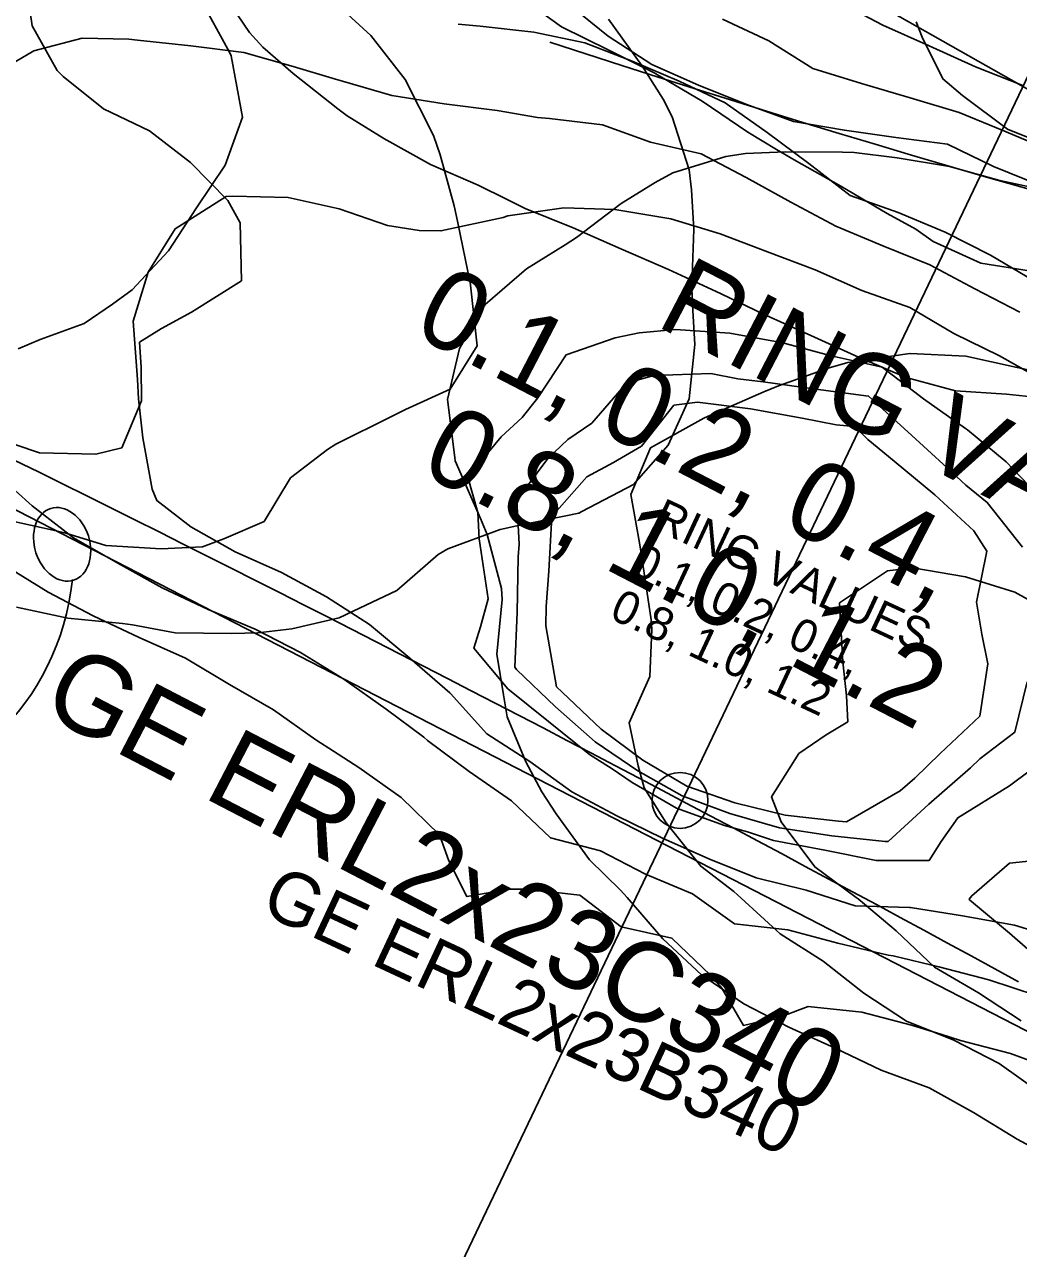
# Model space of a CAD drawing. Extents: x 1638506 to 1658005, y 834807 to 846788.
# Drawn here: x 1640119.8 to 1640269.4, y 842523.2 to 842707.5 of the extents above; entities that cross this region are included whole.
import ezdxf

# ---------------------------------------------------------------- set-up
doc = ezdxf.new("R2010")
doc.units = 0
for name, color, linetype in [('Default', 7, 'Continuous'), ('Old_Level_1', 7, 'Continuous'), ('Old_Level_2', 7, 'Continuous'), ('Scratch_Level_0', 7, 'Continuous')]:
    doc.layers.add(name, color=color, linetype=linetype)

msp = doc.modelspace()

# ---------------------------------------------------------------- linework, layer by layer
at = {"layer": 'Default'}
for p, q in [((1640114.23, 842786.79), (1640314.63, 842672.83)), ((1640060.76, 842664.16), (1640296.3, 842542.72))]:
    msp.add_line(p, q, dxfattribs=at)
msp.add_ellipse((1640125.45, 842629.26), major_axis=(-1.72, 5.4), ratio=0.730797, dxfattribs=at)
msp.add_ellipse((1640097.39, 842627.23), major_axis=(3.78, 34.34), ratio=0.862742, start_param=3.141593, end_param=4.712389, dxfattribs=at)
at = {"layer": 'Old_Level_1'}
for points in [[(1640150.91, 842702.81), (1640150.68, 842703.26), (1640146.14, 842711.64), (1640144.46, 842714.27), (1640140.93, 842718.55), (1640135.28, 842724.54), (1640129.23, 842729.66), (1640128.89, 842729.97), (1640123.18, 842734.8), (1640116.77, 842739.16)], [(1640242.12, 842711.05), (1640248.95, 842707.43), (1640255.95, 842704.3), (1640262.94, 842701.14), (1640270.07, 842698.37)], [(1640201.34, 842710.84), (1640207.64, 842705.78), (1640214.23, 842701.51), (1640221.23, 842698.38), (1640228.34, 842695.55), (1640235.53, 842692.94), (1640243.19, 842691.62), (1640250.92, 842690.5), (1640258.7, 842689.5), (1640265.63, 842686.17), (1640272.72, 842683.27)], [(1640271.78, 842668.87), (1640265.17, 842672.79), (1640258.36, 842676.29), (1640251.3, 842679.25), (1640244.05, 842681.8), (1640237.84, 842686.59), (1640231.58, 842691.26), (1640225.23, 842695.75), (1640218.3, 842698.98), (1640211.27, 842702.01), (1640204.1, 842704.75), (1640196.43, 842706.39), (1640188.39, 842707.26), (1640185.06, 842707.56)], [(1640224.85, 842708.32), (1640231.8, 842705.06), (1640238.43, 842700.9), (1640245.75, 842698.64), (1640253.11, 842696.5), (1640260.45, 842694.3), (1640267.53, 842691.39), (1640274.58, 842688.4)], [(1640269.62, 842664.23), (1640262.82, 842667.75), (1640256.05, 842671.34), (1640248.95, 842674.22), (1640241.88, 842677.16), (1640235.14, 842680.8), (1640228.42, 842684.49), (1640221.65, 842688.07), (1640214.02, 842689.81), (1640206.8, 842692.43), (1640198.79, 842693.36), (1640196.99, 842693.55), (1640190.92, 842694.58), (1640182.94, 842695.57), (1640175.09, 842696.83), (1640167.66, 842699), (1640166.58, 842699.29), (1640160.24, 842701.19), (1640152.79, 842703.31), (1640144.82, 842704.33), (1640136.79, 842705.2), (1640135.49, 842705.35), (1640128.47, 842705.47), (1640121.19, 842703.57), (1640118.36, 842701.89)], [(1640118.85, 842658.68), (1640122.12, 842660.1), (1640128.79, 842662.49), (1640133.02, 842665.4), (1640135.97, 842667.58), (1640141.47, 842673.46), (1640145.67, 842679.94), (1640150.01, 842686.35), (1640152.58, 842693.6), (1640150.91, 842702.81)], [(1640273.23, 842653.88), (1640266.54, 842657.64), (1640259.68, 842661.02), (1640253.05, 842664.91), (1640245.81, 842667.48), (1640238.81, 842670.57), (1640231.63, 842673.28), (1640224.47, 842676.01), (1640217.08, 842678.28), (1640209.25, 842679.58), (1640208.65, 842679.67), (1640200.97, 842679.93), (1640192.55, 842678.74), (1640191.84, 842678.46), (1640182.47, 842676.46), (1640179.17, 842676.54), (1640174.4, 842677.25), (1640167.15, 842679.8), (1640159.49, 842681.47), (1640151.14, 842681.68), (1640150.16, 842681.63), (1640142.46, 842676.77), (1640138.39, 842670.23), (1640136.12, 842662.85), (1640136.78, 842654.1), (1640136.92, 842651.18), (1640137.59, 842645.28), (1640139.02, 842637.58), (1640139.69, 842635.86), (1640144.81, 842631.91), (1640151.48, 842628.11), (1640158.48, 842625), (1640165.23, 842621.38), (1640171.72, 842617.19), (1640177.78, 842612.1), (1640183.8, 842606.9), (1640183.9, 842606.81), (1640189.35, 842600.71), (1640195.86, 842596.57), (1640202.17, 842591.99), (1640208.93, 842588.39), (1640215.79, 842585), (1640222.8, 842581.92), (1640229.9, 842579.06), (1640237.46, 842577.17), (1640244.82, 842574.84), (1640252.99, 842574.59), (1640253.13, 842574.57), (1640260.98, 842573.3), (1640268.78, 842571.93), (1640276.16, 842569.65)], [(1640273.22, 842635.75), (1640267.53, 842641.66), (1640261.71, 842646.49), (1640261.44, 842646.7), (1640255.08, 842651.15), (1640248.87, 842655.94), (1640241.21, 842657.62), (1640233.71, 842659.63), (1640233.38, 842659.7), (1640225.93, 842661.06), (1640217.75, 842661.62), (1640212.29, 842661.1), (1640208.71, 842660.33), (1640201.31, 842657.77), (1640197.07, 842651.31), (1640194.7, 842648.38), (1640191.54, 842645.45), (1640186.49, 842639.36), (1640188.01, 842634.04), (1640188.24, 842630.1), (1640189.57, 842621.05), (1640188.43, 842616.83), (1640187.41, 842613.61), (1640192.53, 842607.51), (1640198.67, 842602.6), (1640204.8, 842597.63), (1640208.26, 842595.45), (1640211.26, 842593.39), (1640217.91, 842589.54), (1640225.13, 842586.92), (1640228.63, 842585.95), (1640232.53, 842584.69), (1640240.27, 842583.2), (1640247.99, 842581.65), (1640255.94, 842581.65), (1640257.76, 842584.5), (1640260.26, 842588.08), (1640268.05, 842592.89), (1640271.21, 842595.25)], [(1640269.98, 842628.81), (1640264.7, 842635.58), (1640261.45, 842638.17), (1640258.68, 842640.78), (1640252.76, 842646.18), (1640246.84, 842651.58), (1640238.89, 842652.65), (1640230.95, 842653.71), (1640227.17, 842654.16), (1640223.1, 842654.98), (1640214.52, 842654.68), (1640210.37, 842653.55), (1640205.18, 842647.53), (1640201.58, 842645.03), (1640198.55, 842642.18), (1640193.91, 842635.9), (1640194.24, 842629.29), (1640194.11, 842627.37), (1640193.94, 842619), (1640193.57, 842610.74), (1640193.86, 842610.39), (1640199.69, 842604.79), (1640205.68, 842599.52), (1640212.1, 842595.18), (1640218.78, 842591.41), (1640225.96, 842588.72), (1640233.41, 842586.59), (1640241.29, 842585.39), (1640249.33, 842584.52), (1640249.79, 842584.52), (1640255.88, 842590.12), (1640262.18, 842595.63), (1640263.57, 842596.96), (1640268.84, 842600.96), (1640270.68, 842608.54)], [(1640264.79, 842611.29), (1640263.89, 842615.74), (1640263.06, 842620.54), (1640264.63, 842628.25), (1640262.69, 842631.27), (1640256.79, 842636.73), (1640250.7, 842641.77), (1640246.7, 842645.05), (1640244.71, 842647.02), (1640241.93, 842647.27), (1640236.84, 842648.24), (1640229.06, 842649.66), (1640221.09, 842650.67), (1640217.52, 842650.21), (1640212.63, 842644.05), (1640208.42, 842641.6), (1640204.44, 842639.43), (1640199.17, 842633.45), (1640198.71, 842625.22), (1640198.31, 842619.91), (1640198.25, 842617), (1640199.87, 842607.8), (1640200.72, 842606.98), (1640206.56, 842601.42), (1640212.84, 842596.78), (1640219.45, 842592.85), (1640226.71, 842590.32), (1640234.3, 842588.49), (1640242.32, 842587.58), (1640243.49, 842587.46), (1640251.57, 842592.13), (1640253.77, 842594.05), (1640257.58, 842597.77), (1640263.59, 842603.41), (1640264.79, 842611.29)], [(1640118.37, 842637.36), (1640120.95, 842635.04), (1640127.16, 842630.25), (1640133.82, 842626.44), (1640140.52, 842622.7), (1640147.45, 842619.46), (1640154.51, 842616.5), (1640161.31, 842612.98), (1640167.87, 842608.95), (1640174.21, 842604.44), (1640179.91, 842600.23), (1640180.45, 842599.71), (1640186.73, 842595.08), (1640193.09, 842590.62), (1640198.93, 842585.05), (1640206.46, 842583.09), (1640213.27, 842579.6), (1640220.33, 842576.63), (1640226.67, 842572.12), (1640234.69, 842571.22), (1640242.19, 842569.21), (1640249.78, 842567.38), (1640250.52, 842567.3), (1640257.41, 842565.64), (1640264.94, 842563.69), (1640272.24, 842561.26)], [(1640116.79, 842626.12), (1640123.33, 842622.05), (1640130.13, 842618.51), (1640137.04, 842615.24), (1640144.04, 842612.14), (1640150.62, 842608.15), (1640157.27, 842604.32), (1640163.61, 842599.82), (1640166.28, 842598.14), (1640170.11, 842595.65), (1640176.46, 842591.16), (1640182.27, 842585.52), (1640183.63, 842581.61), (1640186.38, 842576.22), (1640192.78, 842577.34), (1640195.33, 842577.32), (1640203.36, 842576.44), (1640209.58, 842571.68), (1640217.22, 842569.97), (1640223.06, 842564.39), (1640224.72, 842562.45), (1640227.98, 842556.83), (1640233.86, 842558.19), (1640237.74, 842559.66), (1640245.79, 842558.83), (1640253.31, 842556.85), (1640257.68, 842555.52), (1640260.68, 842554.56), (1640268.21, 842552.59), (1640275.41, 842549.95)]]:
    msp.add_lwpolyline(points, dxfattribs=at)
msp.add_circle((1640218.45, 842590.7), 4.21, dxfattribs=at)
at = {"layer": 'Old_Level_2'}
msp.add_line((1640319.78, 842802.51), (1640164.82, 842477.58), dxfattribs=at)
for centre, radius, start, end in [((1640787.74, 844492.39), 1882, 251.76578, 273.94492), ((1638364.53, 839083.08), 3967.5, 61.30704, 65.05582)]:
    msp.add_arc(centre, radius, start, end, dxfattribs=at)
at = {"layer": 'Scratch_Level_0'}
for points in [[(1640186.93, 842668.27), (1640186.91, 842668.37), (1640184.98, 842677.91), (1640184.46, 842680.23), (1640182.35, 842687.89), (1640181.33, 842690.81), (1640177.08, 842699.23), (1640177.06, 842699.26), (1640171.92, 842705.88), (1640166.08, 842711.23), (1640160.28, 842716.6), (1640160.26, 842716.62), (1640154.71, 842722.53), (1640149.4, 842728.92), (1640145.99, 842732.64), (1640143.88, 842734.89), (1640138.25, 842740.64), (1640132.68, 842746.51), (1640129.19, 842749.98), (1640127.18, 842752.52), (1640121.22, 842757.64), (1640114.3, 842760.92)], [(1640152.23, 842677.67), (1640150.4, 842681.05), (1640144.75, 842686.76), (1640138.59, 842691.5), (1640131.7, 842694.83), (1640125.6, 842699.69), (1640124.7, 842700.6), (1640120.95, 842707.33), (1640120.34, 842711.48), (1640120.44, 842720.05), (1640120.21, 842722.51), (1640119, 842729.42)], [(1640148.97, 842713.26), (1640153.64, 842706.31), (1640155.68, 842704.12), (1640160.21, 842700.17), (1640166.95, 842694.85), (1640168.35, 842693.79), (1640173.86, 842690.37), (1640180.88, 842686.45), (1640188.06, 842683.35), (1640192.41, 842681.2), (1640195.16, 842679.82), (1640202.39, 842676.94), (1640209.56, 842673.78), (1640216.73, 842670.63), (1640223.87, 842667.32), (1640224.62, 842666.98), (1640231, 842663.94), (1640238.16, 842660.72), (1640245.31, 842657.45), (1640252.49, 842654.38), (1640259.9, 842652.39), (1640267.6, 842651.88), (1640275.23, 842651.06)], [(1640193.83, 842712.12), (1640200.62, 842707.19), (1640207.71, 842703.67), (1640214.78, 842700.14), (1640214.81, 842700.13), (1640221.78, 842695.99), (1640228.66, 842691.33), (1640232.97, 842688.71), (1640235.62, 842687.14), (1640242.63, 842683.18), (1640249.62, 842679.1), (1640253.94, 842676.74), (1640256.57, 842674.86), (1640263.73, 842671.6), (1640271.28, 842670.38)], [(1640220.69, 842659.36), (1640220.27, 842666.19), (1640220.22, 842668.22), (1640220.54, 842676.67), (1640220.19, 842682.64), (1640219.83, 842685.67), (1640217.28, 842693.64), (1640215.93, 842696.31), (1640212.68, 842701.37), (1640207.69, 842708.36)], [(1640254, 842707.92), (1640254.91, 842705.63), (1640257.99, 842699.33), (1640260.96, 842696.84), (1640267.74, 842691.75), (1640274.97, 842688.86)], [(1640271.32, 842683.02), (1640266.58, 842684.06), (1640259.03, 842686.14), (1640251.11, 842687.47), (1640244.67, 842688.24), (1640242.91, 842688.3), (1640234.33, 842688.36), (1640228.31, 842688.11), (1640225.35, 842687.68), (1640217.37, 842685.18), (1640214.69, 842683.74), (1640209.6, 842680.59), (1640202.88, 842675.47), (1640201.18, 842674.34), (1640195.35, 842670.75), (1640189.14, 842665.36), (1640185.27, 842658.75), (1640183.43, 842651.09), (1640184.57, 842642.36), (1640184.63, 842641.84), (1640188.4, 842633.14), (1640189.4, 842630.74), (1640191.56, 842622.63), (1640191.68, 842620.94), (1640190.86, 842612.74), (1640191.87, 842606.62), (1640192.45, 842603.3), (1640195.23, 842596.5), (1640197.66, 842591.97), (1640199.8, 842588.7), (1640204.82, 842581.77), (1640209.48, 842577.21), (1640210.5, 842576.1), (1640215.87, 842569.85), (1640221.69, 842564.46), (1640228.04, 842560.08), (1640234.82, 842556.55), (1640241.8, 842553.38), (1640248.7, 842550.07), (1640255.95, 842547.43), (1640262.64, 842543.72), (1640269.18, 842539.7), (1640275.93, 842536.1)], [(1640114.7, 842645.52), (1640122.05, 842643.06), (1640130.54, 842642.82), (1640134.45, 842643.81), (1640137.41, 842650.89), (1640137.34, 842655.92), (1640137.09, 842659.68), (1640140.39, 842661.77), (1640144.9, 842664.24), (1640152.44, 842668.95), (1640152.23, 842677.67)], [(1640116.81, 842632.98), (1640124.56, 842631.3), (1640126.02, 842630.95), (1640132.02, 842629.07), (1640140.38, 842628.57), (1640146.56, 842628.9), (1640149.79, 842630.08), (1640155.85, 842632.69), (1640159.8, 842639.26), (1640165.4, 842643.55), (1640166.66, 842644.32), (1640175.14, 842648.54), (1640177.13, 842649.54), (1640183.85, 842652.63), (1640187.91, 842659.14), (1640186.93, 842668.27)], [(1640118.58, 842619.78), (1640126.33, 842618.12), (1640134.54, 842617.32), (1640136.03, 842617.13), (1640142.44, 842615.94), (1640151, 842615.82), (1640154.91, 842615.94), (1640160.01, 842616.56), (1640167.17, 842618.19), (1640170.22, 842619.63), (1640175.81, 842622.33), (1640182.04, 842627.71), (1640183.49, 842628.59), (1640191.37, 842631.48), (1640193.91, 842632.04), (1640203.2, 842633.96), (1640203.65, 842634.21), (1640211.45, 842638.29), (1640216.66, 842644.21), (1640219.84, 842651.18), (1640220.69, 842659.36)], [(1640276.92, 842654.25), (1640269.19, 842655.91), (1640261.45, 842657.61), (1640253.08, 842658.01), (1640253.04, 842658.01), (1640243.71, 842656.64), (1640240.74, 842655.8), (1640233.26, 842653.12), (1640231.06, 842652.21), (1640222.14, 842648.3), (1640222.05, 842648.26), (1640214.03, 842643.81), (1640211.03, 842636.75), (1640212.36, 842629.48), (1640212.69, 842627.27), (1640214.11, 842617.91), (1640214.21, 842616.43), (1640213.93, 842609.38), (1640210.82, 842602.38), (1640212.17, 842595.92), (1640213.06, 842592.59), (1640216.34, 842587.35), (1640221.56, 842580.8), (1640226.55, 842576.97), (1640227.67, 842575.98), (1640233.51, 842570.6), (1640239.98, 842566.48), (1640246.1, 842561.66), (1640252.55, 842557.48), (1640259.68, 842554.62), (1640266.48, 842551.1), (1640272.76, 842546.6)], [(1640275.55, 842618.35), (1640268.86, 842622.07), (1640261.44, 842624.39), (1640253.51, 842625.72), (1640249.7, 842625.28), (1640242.44, 842620.43), (1640242.93, 842611.56), (1640243.5, 842606.45), (1640243.69, 842602.54), (1640240.46, 842600.59), (1640236.31, 842597.76), (1640232.22, 842591.26), (1640233.66, 842587.5), (1640238.74, 842580.69), (1640244.98, 842576.09), (1640245.26, 842575.87), (1640250.97, 842571.04), (1640256.77, 842565.6), (1640263.37, 842561.72), (1640269.8, 842557.5)], [(1640273.83, 842581.86), (1640268.04, 842581.27), (1640262.35, 842576.35), (1640261.97, 842575.81), (1640262.03, 842575.74), (1640268.05, 842570.73), (1640273.97, 842565.52)]]:
    msp.add_lwpolyline(points, dxfattribs=at)

# ---------------------------------------------------------------- texts
at = {"layer": 'Old_Level_1'}
for s, height, p in [('RING VALUES', 5, (1640213.97, 842631.79)), ('0.1, 0.2, 0.4,', 5, (1640210.8, 842624.99)), ('0.8, 1.0, 1.2', 5, (1640207.63, 842618.2)), ('GE ERL2x23B340', 8, (1640155, 842573.92))]:
    msp.add_text(s, height=height, rotation=335, dxfattribs=at).set_placement(p)
at = {"layer": 'Scratch_Level_0'}
for s, p in [('RING VALUES', (1640214.56, 842662.3)), ('0.1, 0.2, 0.4,', (1640177.89, 842661.06)), ('0.8, 1.0, 1.2', (1640178.97, 842640.21)), ('GE ERL2x23C340', (1640121.89, 842604.03))]:
    msp.add_text(s, height=12, rotation=332.5519, dxfattribs=at).set_placement(p)

doc.saveas('drawing.dxf')
